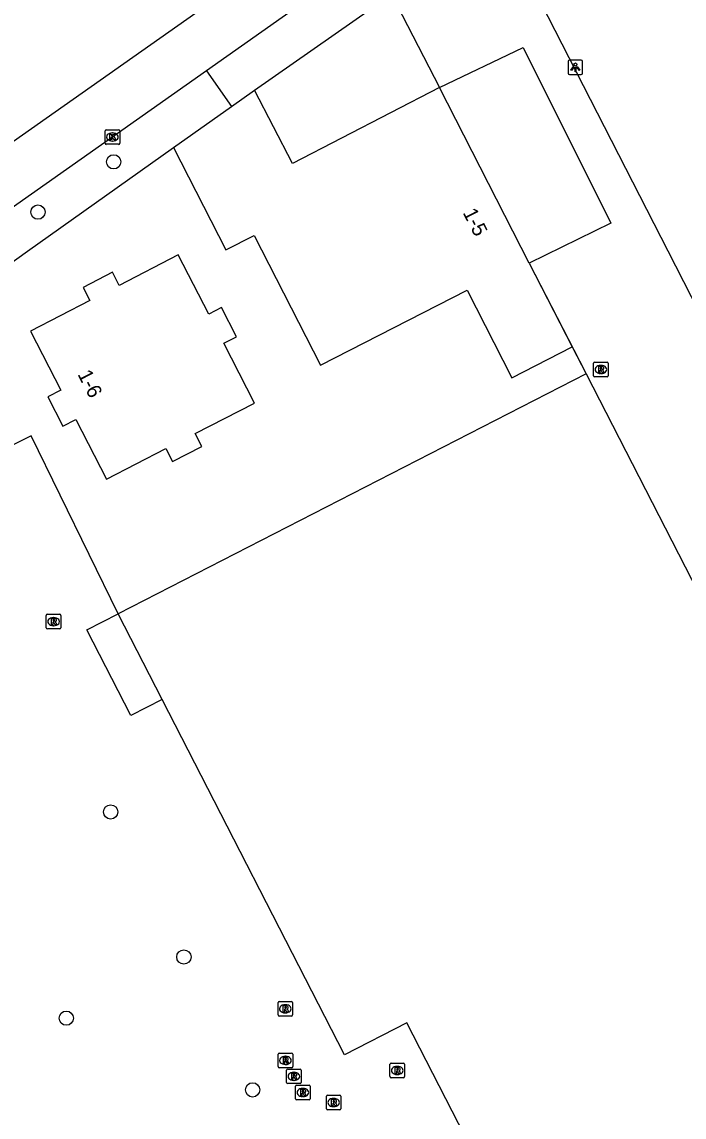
# Model space of a CAD drawing. Extents: x 159353 to 160616, y 385893 to 387321.
# Drawn here: x 159714.5 to 159759.9, y 386440.7 to 386515.7 of the extents above; entities that cross this region are included whole.
import ezdxf

# ---------------------------------------------------------------- set-up
doc = ezdxf.new("R2010")
doc.units = 0
for name, color, linetype in [('IMGEO_Boom', 7, 'Continuous'), ('IMGEO_Fietspad_open', 7, 'Continuous'), ('IMGEO_Groenvoorziening', 7, 'Continuous'), ('IMGEO_Kolk', 7, 'Continuous'), ('IMGEO_Lichtpunt', 7, 'Continuous'), ('IMGEO_Muur', 7, 'Continuous'), ('IMGEO_Pand', 7, 'Continuous'), ('IMGEO_Pand_nummerreeks', 7, 'Continuous'), ('IMGEO_Parkeervlak_open', 7, 'Continuous'), ('IMGEO_Rioolput', 7, 'Continuous'), ('IMGEO_Voetpad_open', 7, 'Continuous')]:
    doc.layers.add(name, color=color, linetype=linetype)

msp = doc.modelspace()

# ---------------------------------------------------------------- linework, layer by layer
at = {"layer": 'IMGEO_Boom'}
for centre in [(159720.759, 386506.135), (159715.566, 386502.688), (159720.552, 386461.57), (159725.572, 386451.629), (159717.509, 386447.435), (159730.284, 386442.517)]:
    msp.add_circle(centre, 0.489, dxfattribs=at)
at = {"layer": 'IMGEO_Fietspad_open'}
for points in [[(159713.275, 386507.109), (159733.956, 386521.697)], [(159739.906, 386521.405), (159727.124, 386512.381)], [(159727.124, 386512.381), (159713.737, 386502.945)]]:
    msp.add_lwpolyline(points, dxfattribs=at)
at = {"layer": 'IMGEO_Groenvoorziening'}
msp.add_lwpolyline([(159710.677, 386497.027), (159714.857, 386500), (159724.863, 386507.117)], dxfattribs=at)
at = {"layer": 'IMGEO_Kolk'}
for p, q in [((159720.171, 386507.407), (159720.171, 386508.259)), ((159720.246, 386508.333), (159721.098, 386508.333)), ((159720.659, 386508.113), (159720.684, 386508.113)), ((159721.172, 386508.259), (159721.172, 386507.407)), ((159721.098, 386507.333), (159720.246, 386507.333)), ((159720.682, 386507.553), (159720.657, 386507.553))]:
    msp.add_line(p, q, dxfattribs=at)
for points in [[(159720.171, 386507.407), (159720.171, 386508.259)], [(159720.246, 386508.333), (159721.098, 386508.333)], [(159721.172, 386508.259), (159721.172, 386507.407)], [(159721.098, 386507.333), (159720.246, 386507.333)], [(159720.492, 386508.033), (159720.615, 386508.033), (159720.615, 386507.882), (159720.745, 386508.033), (159720.909, 386508.033), (159720.763, 386507.882), (159720.916, 386507.633), (159720.764, 386507.633), (159720.679, 386507.797), (159720.615, 386507.73), (159720.615, 386507.633), (159720.492, 386507.633), (159720.492, 386508.033)]]:
    msp.add_lwpolyline(points, dxfattribs=at)
for centre, start, end in [((159720.248, 386508.257), 91.55205, 178.44795), ((159720.248, 386508.257), 91.55205, 178.44795), ((159721.096, 386508.257), 1.55205, 88.44795), ((159721.096, 386508.257), 1.55205, 88.44795), ((159720.248, 386507.409), 181.55205, 268.44795), ((159720.248, 386507.409), 181.55205, 268.44795), ((159721.096, 386507.409), 271.55205, 358.44795), ((159721.096, 386507.409), 271.55205, 358.44795)]:
    msp.add_arc(centre, 0.0765, start, end, dxfattribs=at)
for centre, major_axis, ratio, start_param, end_param in [((159720.658, 386507.833), (-0.387, 0.002), 0.722429, 4.712389, 7.853982), ((159720.683, 386507.833), (-0.39, 0.002), 0.717154, 1.570796, 4.712389)]:
    msp.add_ellipse(centre, major_axis=major_axis, ratio=ratio, start_param=start_param, end_param=end_param, dxfattribs=at)
at = {"layer": 'IMGEO_Lichtpunt'}
for p, q in [((159751.915, 386513.012), (159751.915, 386512.205)), ((159751.915, 386513.012), (159751.915, 386512.205)), ((159752.817, 386513.107), (159752.009, 386513.107)), ((159752.817, 386513.107), (159752.009, 386513.107)), ((159752.911, 386512.205), (159752.911, 386513.012)), ((159752.911, 386512.205), (159752.911, 386513.012)), ((159752.009, 386512.111), (159752.817, 386512.111)), ((159752.009, 386512.111), (159752.817, 386512.111))]:
    msp.add_line(p, q, dxfattribs=at)
for points in [[(159752.289, 386512.676), (159752.328, 386512.648), (159752.14, 386512.386), (159752.102, 386512.413), (159752.289, 386512.676)], [(159752.391, 386512.628), (159752.438, 386512.628), (159752.438, 386512.306), (159752.391, 386512.306), (159752.391, 386512.628)], [(159752.501, 386512.648), (159752.539, 386512.675), (159752.726, 386512.413), (159752.687, 386512.385), (159752.501, 386512.648)]]:
    msp.add_lwpolyline(points, dxfattribs=at)
msp.add_circle((159752.414, 386512.81), 0.0994, dxfattribs=at)
for centre, start, end in [((159752.009, 386513.012), 90, 180), ((159752.009, 386513.012), 90, 180), ((159752.817, 386513.012), 0, 90), ((159752.817, 386513.012), 0, 90), ((159752.009, 386512.205), 180, 270), ((159752.009, 386512.205), 180, 270), ((159752.817, 386512.205), 270, 0), ((159752.817, 386512.205), 270, 360)]:
    msp.add_arc(centre, 0.0946, start, end, dxfattribs=at)
at = {"layer": 'IMGEO_Muur'}
for points in [[(159749.253, 386499.194), (159753.082, 386491.732)], [(159715.095, 386487.344), (159711.798, 386485.698), (159707.227, 386494.853)]]:
    msp.add_lwpolyline(points, dxfattribs=at)
at = {"layer": 'IMGEO_Pand'}
for points in [[(159743.087, 386511.24), (159733.014, 386506.017), (159730.408, 386511.042)], [(159749.257, 386499.196), (159743.087, 386511.24)], [(159728.827, 386509.923), (159730.408, 386511.042)], [(159724.863, 386507.117), (159728.827, 386509.923)], [(159724.863, 386507.117), (159728.457, 386500.102), (159730.385, 386501.09), (159734.941, 386492.196), (159744.984, 386497.34), (159748.063, 386491.329), (159752.201, 386493.449)], [(159728.304, 386493.692), (159729.184, 386494.146), (159728.148, 386496.148), (159727.272, 386495.697), (159725.183, 386499.757), (159721.132, 386497.665), (159720.67, 386498.559), (159718.662, 386497.521), (159719.123, 386496.628), (159715.058, 386494.529), (159717.139, 386490.474), (159716.246, 386490.023), (159717.283, 386488.003), (159718.172, 386488.461), (159720.26, 386484.391), (159724.333, 386486.478), (159724.789, 386485.587), (159726.796, 386486.615), (159726.34, 386487.506), (159730.414, 386489.594), (159728.304, 386493.692)], [(159749.257, 386499.196), (159752.201, 386493.449)], [(159753.152, 386491.592), (159721.076, 386475.16)], [(159753.152, 386491.592), (159765.356, 386467.81)], [(159724.093, 386469.28), (159721.076, 386475.16)], [(159755.254, 386431.554), (159750.18, 386428.951), (159740.866, 386447.103), (159736.596, 386444.912), (159724.093, 386469.28)]]:
    msp.add_lwpolyline(points, dxfattribs=at)
at = {"layer": 'IMGEO_Parkeervlak_open'}
msp.add_lwpolyline([(159721.076, 386475.16), (159715.095, 386487.344), (159711.798, 386485.698), (159707.227, 386494.853)], dxfattribs=at)
at = {"layer": 'IMGEO_Rioolput'}
for p, q in [((159753.662, 386491.475), (159753.662, 386492.327)), ((159753.737, 386492.401), (159754.589, 386492.401)), ((159754.663, 386492.327), (159754.663, 386491.475)), ((159754.173, 386491.621), (159754.148, 386491.621)), ((159754.15, 386492.181), (159754.175, 386492.181)), ((159754.589, 386491.401), (159753.737, 386491.401)), ((159716.215, 386475.116), (159717.067, 386475.116)), ((159716.14, 386474.19), (159716.14, 386475.042)), ((159716.651, 386474.336), (159716.626, 386474.336)), ((159716.628, 386474.896), (159716.653, 386474.896)), ((159717.141, 386475.042), (159717.141, 386474.19)), ((159717.067, 386474.116), (159716.215, 386474.116)), ((159732.027, 386447.651), (159732.027, 386448.503)), ((159732.102, 386448.577), (159732.954, 386448.577)), ((159732.515, 386448.357), (159732.54, 386448.357)), ((159733.028, 386448.503), (159733.028, 386447.651)), ((159732.954, 386447.577), (159732.102, 386447.577)), ((159732.538, 386447.797), (159732.513, 386447.797)), ((159732.109, 386445.039), (159732.961, 386445.039)), ((159732.034, 386444.113), (159732.034, 386444.965)), ((159732.522, 386444.819), (159732.547, 386444.819)), ((159733.035, 386444.965), (159733.035, 386444.113)), ((159739.704, 386443.424), (159739.704, 386444.276)), ((159739.779, 386444.35), (159740.631, 386444.35)), ((159740.705, 386444.276), (159740.705, 386443.424)), ((159732.961, 386444.039), (159732.109, 386444.039)), ((159732.545, 386444.259), (159732.52, 386444.259)), ((159732.614, 386443.019), (159732.614, 386443.871)), ((159732.689, 386443.945), (159733.541, 386443.945)), ((159733.102, 386443.725), (159733.127, 386443.725)), ((159733.615, 386443.871), (159733.615, 386443.019)), ((159740.215, 386443.57), (159740.19, 386443.57)), ((159740.192, 386444.13), (159740.217, 386444.13)), ((159733.541, 386442.945), (159732.689, 386442.945)), ((159733.125, 386443.165), (159733.1, 386443.165)), ((159733.305, 386442.838), (159734.157, 386442.838)), ((159740.631, 386443.35), (159739.779, 386443.35)), ((159733.23, 386441.912), (159733.23, 386442.764)), ((159733.741, 386442.058), (159733.716, 386442.058)), ((159733.718, 386442.618), (159733.743, 386442.618)), ((159734.231, 386442.764), (159734.231, 386441.912)), ((159735.341, 386441.225), (159735.341, 386442.077)), ((159735.416, 386442.151), (159736.268, 386442.151)), ((159736.342, 386442.077), (159736.342, 386441.225)), ((159734.157, 386441.838), (159733.305, 386441.838)), ((159735.852, 386441.371), (159735.827, 386441.371)), ((159735.829, 386441.931), (159735.854, 386441.931)), ((159736.268, 386441.151), (159735.416, 386441.151))]:
    msp.add_line(p, q, dxfattribs=at)
for points in [[(159753.662, 386491.475), (159753.662, 386492.327)], [(159753.737, 386492.401), (159754.589, 386492.401)], [(159754.663, 386492.327), (159754.663, 386491.475)], [(159754.251, 386492.099), (159753.999, 386492.101), (159753.999, 386491.701)], [(159753.999, 386491.701), (159754.123, 386491.701), (159754.123, 386491.863), (159754.134, 386491.863)], [(159754.177, 386492.02), (159754.123, 386492.02), (159754.123, 386491.939)], [(159754.123, 386491.939), (159754.175, 386491.939)], [(159754.181, 386491.834), (159754.252, 386491.701), (159754.392, 386491.701), (159754.327, 386491.827)], [(159754.589, 386491.401), (159753.737, 386491.401)], [(159716.215, 386475.116), (159717.067, 386475.116)], [(159716.14, 386474.19), (159716.14, 386475.042)], [(159716.729, 386474.814), (159716.477, 386474.816), (159716.477, 386474.416)], [(159716.477, 386474.416), (159716.601, 386474.416), (159716.601, 386474.578), (159716.612, 386474.578)], [(159716.655, 386474.735), (159716.601, 386474.735), (159716.601, 386474.654)], [(159716.601, 386474.654), (159716.653, 386474.654)], [(159716.659, 386474.549), (159716.73, 386474.416), (159716.87, 386474.416), (159716.805, 386474.542)], [(159717.141, 386475.042), (159717.141, 386474.19)], [(159717.067, 386474.116), (159716.215, 386474.116)], [(159732.027, 386447.651), (159732.027, 386448.503)], [(159732.102, 386448.577), (159732.954, 386448.577)], [(159732.616, 386448.275), (159732.364, 386448.277), (159732.364, 386447.877)], [(159732.364, 386447.877), (159732.488, 386447.877), (159732.488, 386448.039), (159732.499, 386448.039)], [(159732.542, 386448.196), (159732.488, 386448.196), (159732.488, 386448.115)], [(159732.488, 386448.115), (159732.54, 386448.115)], [(159733.028, 386448.503), (159733.028, 386447.651)], [(159732.954, 386447.577), (159732.102, 386447.577)], [(159732.546, 386448.01), (159732.617, 386447.877), (159732.757, 386447.877), (159732.692, 386448.003)], [(159732.109, 386445.039), (159732.961, 386445.039)], [(159732.034, 386444.113), (159732.034, 386444.965)], [(159732.623, 386444.737), (159732.371, 386444.739), (159732.371, 386444.339)], [(159732.371, 386444.339), (159732.495, 386444.339), (159732.495, 386444.501), (159732.506, 386444.501)], [(159732.549, 386444.658), (159732.495, 386444.658), (159732.495, 386444.577)], [(159732.495, 386444.577), (159732.547, 386444.577)], [(159732.553, 386444.472), (159732.624, 386444.339), (159732.764, 386444.339), (159732.699, 386444.465)], [(159733.035, 386444.965), (159733.035, 386444.113)], [(159739.704, 386443.424), (159739.704, 386444.276)], [(159739.779, 386444.35), (159740.631, 386444.35)], [(159740.705, 386444.276), (159740.705, 386443.424)], [(159732.961, 386444.039), (159732.109, 386444.039)], [(159732.614, 386443.019), (159732.614, 386443.871)], [(159732.689, 386443.945), (159733.541, 386443.945)], [(159733.203, 386443.643), (159732.951, 386443.645), (159732.951, 386443.245)], [(159733.129, 386443.564), (159733.075, 386443.564), (159733.075, 386443.483)], [(159733.615, 386443.871), (159733.615, 386443.019)], [(159740.293, 386444.048), (159740.041, 386444.05), (159740.041, 386443.65)], [(159740.041, 386443.65), (159740.165, 386443.65), (159740.165, 386443.812), (159740.176, 386443.812)], [(159740.219, 386443.969), (159740.165, 386443.969), (159740.165, 386443.888)], [(159740.165, 386443.888), (159740.217, 386443.888)], [(159740.223, 386443.783), (159740.294, 386443.65), (159740.434, 386443.65), (159740.369, 386443.776)], [(159733.541, 386442.945), (159732.689, 386442.945)], [(159732.951, 386443.245), (159733.075, 386443.245), (159733.075, 386443.407), (159733.086, 386443.407)], [(159733.075, 386443.483), (159733.127, 386443.483)], [(159733.133, 386443.378), (159733.204, 386443.245), (159733.344, 386443.245), (159733.279, 386443.371)], [(159733.305, 386442.838), (159734.157, 386442.838)], [(159740.631, 386443.35), (159739.779, 386443.35)], [(159733.23, 386441.912), (159733.23, 386442.764)], [(159733.819, 386442.536), (159733.567, 386442.538), (159733.567, 386442.138)], [(159733.567, 386442.138), (159733.691, 386442.138), (159733.691, 386442.3), (159733.702, 386442.3)], [(159733.745, 386442.457), (159733.691, 386442.457), (159733.691, 386442.376)], [(159733.691, 386442.376), (159733.743, 386442.376)], [(159733.749, 386442.271), (159733.82, 386442.138), (159733.96, 386442.138), (159733.895, 386442.264)], [(159734.231, 386442.764), (159734.231, 386441.912)], [(159735.341, 386441.225), (159735.341, 386442.077)], [(159735.416, 386442.151), (159736.268, 386442.151)], [(159736.342, 386442.077), (159736.342, 386441.225)], [(159734.157, 386441.838), (159733.305, 386441.838)], [(159735.93, 386441.849), (159735.678, 386441.851), (159735.678, 386441.451)], [(159735.678, 386441.451), (159735.802, 386441.451), (159735.802, 386441.613), (159735.813, 386441.613)], [(159735.856, 386441.77), (159735.802, 386441.77), (159735.802, 386441.689)], [(159735.802, 386441.689), (159735.854, 386441.689)], [(159735.86, 386441.584), (159735.931, 386441.451), (159736.071, 386441.451), (159736.006, 386441.577)], [(159736.268, 386441.151), (159735.416, 386441.151)]]:
    msp.add_lwpolyline(points, dxfattribs=at)
for centre, radius, start, end in [((159753.739, 386492.325), 0.0765, 91.55205, 178.44795), ((159753.739, 386492.325), 0.0765, 91.55205, 178.44795), ((159754.587, 386492.325), 0.0765, 1.55205, 88.44795), ((159754.587, 386492.325), 0.0765, 1.55205, 88.44795), ((159754.133, 386491.81), 0.0533, 26.02933, 88.69889), ((159754.159, 386492.128), 0.19, 274.7715, 282.96867), ((159754.183, 386491.924), 0.0964, 77.00612, 93.18647), ((159754.197, 386491.981), 0.0378, 276.66336, 79.67722), ((159754.25, 386491.989), 0.109, 350.36119, 89.41601), ((159754.248, 386491.989), 0.112, 277.58423, 350.98172), ((159754.232, 386491.774), 0.108, 29.51342, 73.79051), ((159753.739, 386491.477), 0.0765, 181.55205, 268.44795), ((159753.739, 386491.477), 0.0765, 181.55205, 268.44795), ((159754.587, 386491.477), 0.0765, 271.55205, 358.44795), ((159754.587, 386491.477), 0.0765, 271.55205, 358.44795), ((159716.217, 386475.04), 0.0765, 91.55205, 178.44795), ((159716.217, 386475.04), 0.0765, 91.55205, 178.44795), ((159717.065, 386475.04), 0.0765, 1.55205, 88.44795), ((159717.065, 386475.04), 0.0765, 1.55205, 88.44795), ((159716.611, 386474.525), 0.0533, 26.02933, 88.69889), ((159716.637, 386474.843), 0.19, 274.7715, 282.96867), ((159716.661, 386474.639), 0.0964, 77.00612, 93.18647), ((159716.675, 386474.696), 0.0378, 276.66336, 79.67722), ((159716.728, 386474.704), 0.109, 350.36119, 89.41601), ((159716.726, 386474.704), 0.112, 277.58423, 350.98172), ((159716.71, 386474.489), 0.108, 29.51342, 73.79051), ((159716.217, 386474.192), 0.0765, 181.55205, 268.44795), ((159716.217, 386474.192), 0.0765, 181.55205, 268.44795), ((159717.065, 386474.192), 0.0765, 271.55205, 358.44795), ((159717.065, 386474.192), 0.0765, 271.55205, 358.44795), ((159732.104, 386448.501), 0.0765, 91.55205, 178.44795), ((159732.104, 386448.501), 0.0765, 91.55205, 178.44795), ((159732.498, 386447.986), 0.0533, 26.02933, 88.69889), ((159732.524, 386448.304), 0.19, 274.7715, 282.96867), ((159732.548, 386448.1), 0.0964, 77.00612, 93.18647), ((159732.562, 386448.157), 0.0378, 276.66336, 79.67722), ((159732.615, 386448.165), 0.109, 350.36119, 89.41601), ((159732.613, 386448.165), 0.112, 277.58423, 350.98172), ((159732.597, 386447.95), 0.108, 29.51342, 73.79051), ((159732.952, 386448.501), 0.0765, 1.55205, 88.44795), ((159732.952, 386448.501), 0.0765, 1.55205, 88.44795), ((159732.104, 386447.653), 0.0765, 181.55205, 268.44795), ((159732.104, 386447.653), 0.0765, 181.55205, 268.44795), ((159732.952, 386447.653), 0.0765, 271.55205, 358.44795), ((159732.952, 386447.653), 0.0765, 271.55205, 358.44795), ((159732.111, 386444.963), 0.0765, 91.55205, 178.44795), ((159732.111, 386444.963), 0.0765, 91.55205, 178.44795), ((159732.959, 386444.963), 0.0765, 1.55205, 88.44795), ((159732.959, 386444.963), 0.0765, 1.55205, 88.44795), ((159732.505, 386444.448), 0.0533, 26.02933, 88.69889), ((159732.531, 386444.766), 0.19, 274.7715, 282.96867), ((159732.555, 386444.562), 0.0964, 77.00612, 93.18647), ((159732.569, 386444.619), 0.0378, 276.66336, 79.67722), ((159732.622, 386444.627), 0.109, 350.36119, 89.41601), ((159732.62, 386444.627), 0.112, 277.58423, 350.98172), ((159732.604, 386444.412), 0.108, 29.51342, 73.79051), ((159739.781, 386444.274), 0.0765, 91.55205, 178.44795), ((159739.781, 386444.274), 0.0765, 91.55205, 178.44795), ((159740.629, 386444.274), 0.0765, 1.55205, 88.44795), ((159740.629, 386444.274), 0.0765, 1.55205, 88.44795), ((159732.111, 386444.115), 0.0765, 181.55205, 268.44795), ((159732.111, 386444.115), 0.0765, 181.55205, 268.44795), ((159732.691, 386443.869), 0.0765, 91.55205, 178.44795), ((159732.691, 386443.869), 0.0765, 91.55205, 178.44795), ((159732.959, 386444.115), 0.0765, 271.55205, 358.44795), ((159732.959, 386444.115), 0.0765, 271.55205, 358.44795), ((159733.135, 386443.468), 0.0964, 77.00612, 93.18647), ((159733.149, 386443.525), 0.0378, 276.66336, 79.67722), ((159733.202, 386443.533), 0.109, 350.36119, 89.41601), ((159733.539, 386443.869), 0.0765, 1.55205, 88.44795), ((159733.539, 386443.869), 0.0765, 1.55205, 88.44795), ((159740.175, 386443.759), 0.0533, 26.02933, 88.69889), ((159740.201, 386444.077), 0.19, 274.7715, 282.96867), ((159740.225, 386443.873), 0.0964, 77.00612, 93.18647), ((159740.239, 386443.93), 0.0378, 276.66336, 79.67722), ((159740.292, 386443.938), 0.109, 350.36119, 89.41601), ((159740.29, 386443.938), 0.112, 277.58423, 350.98172), ((159740.274, 386443.723), 0.108, 29.51342, 73.79051), ((159732.691, 386443.021), 0.0765, 181.55205, 268.44795), ((159732.691, 386443.021), 0.0765, 181.55205, 268.44795), ((159733.085, 386443.354), 0.0533, 26.02933, 88.69889), ((159733.111, 386443.672), 0.19, 274.7715, 282.96867), ((159733.2, 386443.533), 0.112, 277.58423, 350.98172), ((159733.184, 386443.318), 0.108, 29.51342, 73.79051), ((159733.307, 386442.762), 0.0765, 91.55205, 178.44795), ((159733.307, 386442.762), 0.0765, 91.55205, 178.44795), ((159733.539, 386443.021), 0.0765, 271.55205, 358.44795), ((159733.539, 386443.021), 0.0765, 271.55205, 358.44795), ((159734.155, 386442.762), 0.0765, 1.55205, 88.44795), ((159734.155, 386442.762), 0.0765, 1.55205, 88.44795), ((159739.781, 386443.426), 0.0765, 181.55205, 268.44795), ((159739.781, 386443.426), 0.0765, 181.55205, 268.44795), ((159740.629, 386443.426), 0.0765, 271.55205, 358.44795), ((159740.629, 386443.426), 0.0765, 271.55205, 358.44795), ((159733.701, 386442.247), 0.0533, 26.02933, 88.69889), ((159733.727, 386442.565), 0.19, 274.7715, 282.96867), ((159733.751, 386442.361), 0.0964, 77.00612, 93.18647), ((159733.765, 386442.418), 0.0378, 276.66336, 79.67722), ((159733.818, 386442.426), 0.109, 350.36119, 89.41601), ((159733.816, 386442.426), 0.112, 277.58423, 350.98172), ((159733.8, 386442.211), 0.108, 29.51342, 73.79051), ((159735.418, 386442.075), 0.0765, 91.55205, 178.44795), ((159735.418, 386442.075), 0.0765, 91.55205, 178.44795), ((159736.266, 386442.075), 0.0765, 1.55205, 88.44795), ((159736.266, 386442.075), 0.0765, 1.55205, 88.44795), ((159733.307, 386441.914), 0.0765, 181.55205, 268.44795), ((159733.307, 386441.914), 0.0765, 181.55205, 268.44795), ((159734.155, 386441.914), 0.0765, 271.55205, 358.44795), ((159734.155, 386441.914), 0.0765, 271.55205, 358.44795), ((159735.812, 386441.56), 0.0533, 26.02933, 88.69889), ((159735.838, 386441.878), 0.19, 274.7715, 282.96867), ((159735.862, 386441.674), 0.0964, 77.00612, 93.18647), ((159735.876, 386441.731), 0.0378, 276.66336, 79.67722), ((159735.929, 386441.739), 0.109, 350.36119, 89.41601), ((159735.927, 386441.739), 0.112, 277.58423, 350.98172), ((159735.911, 386441.524), 0.108, 29.51342, 73.79051), ((159735.418, 386441.227), 0.0765, 181.55205, 268.44795), ((159735.418, 386441.227), 0.0765, 181.55205, 268.44795), ((159736.266, 386441.227), 0.0765, 271.55205, 358.44795), ((159736.266, 386441.227), 0.0765, 271.55205, 358.44795)]:
    msp.add_arc(centre, radius, start, end, dxfattribs=at)
for centre, major_axis, ratio, start_param, end_param in [((159754.149, 386491.901), (-0.387, 0.002), 0.722429, 4.712389, 7.853982), ((159754.174, 386491.901), (-0.39, 0.002), 0.717154, 1.570796, 4.712389), ((159716.627, 386474.616), (-0.387, 0.002), 0.722429, 4.712389, 7.853982), ((159716.652, 386474.616), (-0.39, 0.002), 0.717154, 1.570796, 4.712389), ((159732.514, 386448.077), (-0.387, 0.002), 0.722429, 4.712389, 7.853982), ((159732.539, 386448.077), (-0.39, 0.002), 0.717154, 1.570796, 4.712389), ((159732.521, 386444.539), (-0.387, 0.002), 0.722429, 4.712389, 7.853982), ((159732.546, 386444.539), (-0.39, 0.002), 0.717154, 1.570796, 4.712389), ((159733.101, 386443.445), (-0.387, 0.002), 0.722429, 4.712389, 7.853982), ((159733.126, 386443.445), (-0.39, 0.002), 0.717154, 1.570796, 4.712389), ((159740.191, 386443.85), (-0.387, 0.002), 0.722429, 4.712389, 7.853982), ((159740.216, 386443.85), (-0.39, 0.002), 0.717154, 1.570796, 4.712389), ((159733.717, 386442.338), (-0.387, 0.002), 0.722429, 4.712389, 7.853982), ((159733.742, 386442.338), (-0.39, 0.002), 0.717154, 1.570796, 4.712389), ((159735.828, 386441.651), (-0.387, 0.002), 0.722429, 4.712389, 7.853982), ((159735.853, 386441.651), (-0.39, 0.002), 0.717154, 1.570796, 4.712389)]:
    msp.add_ellipse(centre, major_axis=major_axis, ratio=ratio, start_param=start_param, end_param=end_param, dxfattribs=at)
at = {"layer": 'IMGEO_Voetpad_open'}
for points in [[(159806.88, 386450.267), (159788.823, 386441.192), (159758.772, 386500), (159746.188, 386524.627)], [(159730.408, 386511.042), (159739.814, 386517.637), (159743.087, 386511.24)], [(159743.087, 386511.24), (159748.84, 386513.971), (159754.838, 386501.94), (159749.257, 386499.196)], [(159727.124, 386512.381), (159728.827, 386509.923)], [(159752.201, 386493.449), (159753.152, 386491.592)], [(159724.093, 386469.28), (159721.942, 386468.177), (159718.925, 386474.058), (159721.076, 386475.16)]]:
    msp.add_lwpolyline(points, dxfattribs=at)

# ---------------------------------------------------------------- texts
at = {"layer": 'IMGEO_Pand_nummerreeks'}
for s, rotation, p in [('1-5', 297.10642, (159744.674, 386502.651)), ('1-6', 297.15799, (159718.263, 386491.571))]:
    msp.add_text(s, height=1, rotation=rotation, dxfattribs=at).set_placement(p)

doc.saveas('drawing.dxf')
